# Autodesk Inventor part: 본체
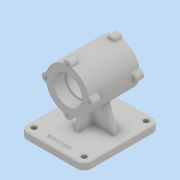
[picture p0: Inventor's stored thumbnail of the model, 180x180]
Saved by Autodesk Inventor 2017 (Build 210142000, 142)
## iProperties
Part Number: 본체
Material: 일반
Document SubType Name: Modeling
Designer: MRC
Density: 1 g/cm^3
Appearance: 기본값
Mass: 452.843 g
Surface Area: 800.379 cm^2
Volume: 452.843 cm^3
Author: MRC
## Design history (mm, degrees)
sketch "스케치1"
  geometry: C1 r 37 at (0, 0); 1 further point
  constraints: 1 centre point, 1 coincident
  dimensions: "d0" = 74 diameter of C1
extrude "돌출1" new body sketch "스케치1" stored distance "d1" = 87; taper "d2" = 0 deg
sketch "스케치2"
  geometry: C1 r 23.5 at (0, 0); 1 further point
  constraints: 1 centre point, 1 coincident
  dimensions: "d3" = 47 diameter of C1
extrude "돌출2" cut sketch "스케치2" distance "d4" = 19; taper "d5" = 0 deg
sketch "스케치3"
  geometry: C1 r 23.5 at (0, 0); 1 further point
  constraints: 1 centre point, 1 coincident
  dimensions: "d6" = 47 diameter of C1
extrude "돌출3" cut sketch "스케치3" distance "d7" = 19; taper "d8" = 0 deg
sketch "스케치4"
  geometry: C1 r 21 at (0, 0); 1 further point
  constraints: 1 centre point, 1 coincident
  dimensions: "d9" = 42 diameter of C1
extrude "돌출4" cut sketch "스케치4" stored distance "d10" = 19; taper "d11" = 0 deg
fillet "모깎기1" dims "d12" = 1
chamfer "모따기1" distance "d13" = 1; stored, may be unused: second distance "d14" = 2, angle "d15" = 45 deg
sketch "스케치5"
  geometry: C1 r 7 at (0, 37); 2 further points
  constraints: 2 vertical alignment, 1 centre point, 1 other
  dimensions: "d16" = 14 diameter of C1
extrude "돌출5" join sketch "스케치5" distance "d17" = 14; taper "d18" = 0 deg
hole "구멍1" diameter "d21" = 3.242; stored, may be unused: countersink angle "d25" = 90 deg, drill point angle "d27" = 118 deg; dims "d19" = 10, "d20" = 10, "d22" = 8, "d23" = 4, "d24" = 2, "d26" = 10
fillet "모깎기2" dims "d31" = 3
fillet "모깎기3" dims "d32" = 3
sketch "스케치6"
  geometry: L1 (-70, 60)-(-82, 60); L2 (-82, 60)-(-82, -70); L3 (-82, -70)-(-70, -70); L4 (-70, -70)-(-70, 60); 1 further point
  constraints: 8 end point, 2 parallel, 1 horizontal, 1 perpendicular
  dimensions: "d33" = 82 distance from line of L2 point (0, 0); "d34" = 12 distance of L2.end L3.end; "d36" = 130 distance of L1.end L2.end; "d37" = 70 distance from line of L3 point (0, 0)
extrude "돌출6" join sketch "스케치6" stored distance "d38" = 110; taper "d39" = 0 deg
fillet "모깎기4" dims "d40" = 12
sketch "스케치7"
  geometry: C1 r 4.5 at (0, 118); C2 r 4.5 at (0, 12); C3 r 4.5 at (86, 12); C4 r 4.5 at (86, 118); A1 r 12 centre (0, 118) between (0, 130) and (-12, 118) reference; A2 r 12 centre (86, 118) between (98, 118) and (86, 130) reference; A3 r 12 centre (86, 12) between (86, 0) and (98, 12) reference; A4 r 12 centre (0, 12) between (-12, 12) and (0, 0) reference; 1 further point
  constraints: 4 centre point, 4 concentric
  dimensions: "d41" = 9 diameter of C1; "d42" = 9 diameter of C2; "d43" = 9 diameter of C3; "d44" = 9 diameter of C4
extrude "돌출7" cut sketch "스케치7" stored distance "d45" = 110; taper "d46" = 0 deg
sketch "스케치8"
  geometry: L1 (-41, -70)-(-28.854, -36.63); L2 (-43, -70)-(43, -70) reference; L3 (-55, -70)-(-55, -82) reference; L4 (-47.5, -70)-(-38.5, -70) reference; 1 further point
  constraints: 2 end point, 1 point on line
  dimensions: "d47" = 14 distance from line of L3 L1.start; "d48" = 110 deg angle of L4 L1
sketch "스케치9"
  geometry: C1 r 5 at (43, 60); 1 further point
  constraints: 1 centre point, 1 coincident
  dimensions: "d49" = 10 diameter of C1
extrude "돌출8" join sketch "스케치9" stored distance "d50" = 110; taper "d51" = 0 deg
feature "리브1" dims "d52" = 1, "d53" = 10, "d54" = 0, "d55" = 0, "d56" = 1, "d57" = 1
sketch "스케치10"
  geometry: L1 (-70, 30)-(-42.679, 20.056); L2 (-70, -58)-(-70, 48) reference; 1 further point
  constraints: 2 end point, 1 point on line
  dimensions: "d58" = 30 vertical distance of L1.start point (0, 0); "d59" = 110 deg angle of L2 L1
feature "리브2" sketch "스케치10" dims "d60" = 1, "d61" = 10, "d62" = 0, "d63" = 0, "d64" = 1, "d65" = 1
fillet "모깎기5" dims "d66" = 3
fillet "모깎기6" dims "d67" = 3
fillet "모깎기7" dims "d68" = 3
sketch "스케치11"
  geometry: 2 further points
  constraints: 1 vertical alignment, 1 other
  dimensions: "d71" = 58 distance of point (43, 57) point (43, 115)
feature "엠보싱1" sketch "스케치11" dims "d2" = 0, "d69" = 0.5, "d70" = 0
node "솔리드1"
pattern_circular "원형 패턴1" dims angle "d29" = 360 deg
mirror "미러1"
mirror "미러2"
mirror "미러3"
